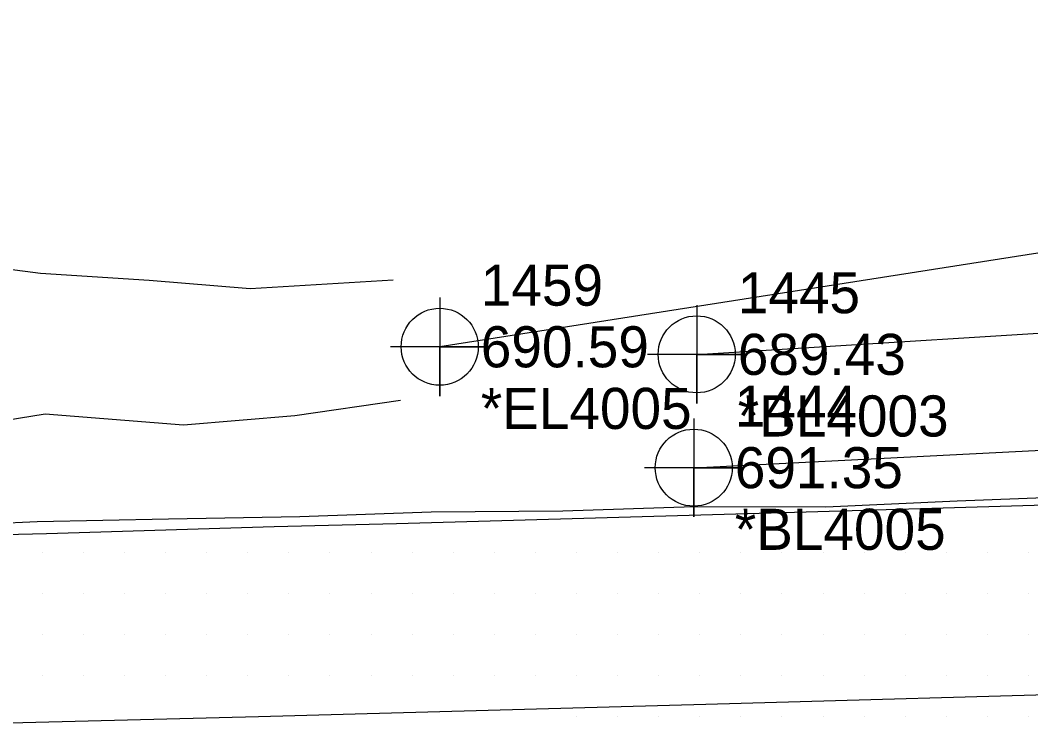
# Model space of a CAD drawing. Extents: x 1755643 to 1760494, y 736519 to 737621.
# Drawn here: x 1757879.9 to 1757941.4, y 736988 to 737031.1 of the extents above; entities that cross this region are included whole.
import ezdxf

# ---------------------------------------------------------------- set-up
doc = ezdxf.new("R2010")
doc.units = 0
for name, color, linetype in [('Exist Horizontal Alignment Direction Label', 7, 'Continuous'), ('Exist Railroads Standard Gauge', 7, 'Continuous'), ('Old_Level_1', 7, 'Continuous'), ('Old_Level_10', 7, 'Continuous'), ('Old_Level_2', 7, 'Continuous'), ('Old_Level_3', 7, 'Continuous'), ('Prop Dimension', 7, 'Continuous'), ('Prop EOT Dash', 7, 'Continuous'), ('Prop Horizontal Alignment Direction Label', 7, 'Continuous'), ('Prop Lane Lines', 7, 'Continuous'), ('Scratch_Level_1', 7, 'Continuous'), ('Scratch_Level_2', 7, 'Continuous'), ('Scratch_Level_5', 7, 'Continuous'), ('Scratch_Level_9', 7, 'Continuous')]:
    doc.layers.add(name, color=color, linetype=linetype)

msp = doc.modelspace()

# ---------------------------------------------------------------- linework, layer by layer
at = {"layer": 'Exist Railroads Standard Gauge'}
for points in [[(1757872.85, 737016.817), (1757881.144, 737015.738), (1757887.747, 737015.311), (1757893.894, 737014.806), (1757902.587, 737015.337)], [(1757871.29, 737005.551), (1757881.423, 737007.182), (1757889.839, 737006.52), (1757896.606, 737007.081), (1757903.049, 737008.017)]]:
    msp.add_lwpolyline(points, dxfattribs=at)
at = {"layer": 'Old_Level_10'}
msp.add_lwpolyline([(1757921.064, 737013.807), (1757921.064, 737007.807), (1757921.064, 737010.807), (1757924.064, 737010.807), (1757918.064, 737010.807)], dxfattribs=at)
msp.add_circle((1757921.064, 737010.807), 2.344, dxfattribs=at)
at = {"layer": 'Prop Dimension'}
msp.add_lwpolyline([(1757921.064, 737010.807), (1757950.306, 737012.625), (1757968.716, 737016.095), (1757981.467, 737016.866)], dxfattribs=at)
at = {"layer": 'Prop Lane Lines'}
for points in [[(1757905.428, 737014.267), (1757905.428, 737008.267), (1757905.428, 737011.267), (1757908.428, 737011.267), (1757902.428, 737011.267)], [(1757920.884, 737006.91), (1757920.884, 737000.91), (1757920.884, 737003.91), (1757923.884, 737003.91), (1757917.884, 737003.91)]]:
    msp.add_lwpolyline(points, dxfattribs=at)
for centre in [(1757905.428, 737011.267), (1757920.884, 737003.91)]:
    msp.add_circle(centre, 2.344, dxfattribs=at)
at = {"layer": 'Scratch_Level_1'}
msp.add_lwpolyline([(1757864.939, 737000.079), (1757872.936, 737000.271), (1757880.928, 737000.627), (1757888.921, 737000.805), (1757896.919, 737000.945), (1757904.914, 737001.227), (1757912.914, 737001.293), (1757920.91, 737001.55), (1757928.913, 737001.535), (1757936.905, 737001.889), (1757944.899, 737002.192), (1757952.901, 737002.259), (1757960.901, 737002.367), (1757968.898, 737002.553), (1757976.895, 737002.778), (1757984.893, 737002.981), (1757992.889, 737003.22), (1758000.882, 737003.602)], dxfattribs=at)
at = {"layer": 'Scratch_Level_2'}
for p, q in [((1757881.25, 736998.75), (1757881.25, 736998.75)), ((1757883.75, 736998.75), (1757883.75, 736998.75)), ((1757886.25, 736998.75), (1757886.25, 736998.75)), ((1757888.75, 736998.75), (1757888.75, 736998.75)), ((1757891.25, 736998.75), (1757891.25, 736998.75)), ((1757893.75, 736998.75), (1757893.75, 736998.75)), ((1757896.25, 736998.75), (1757896.25, 736998.75)), ((1757898.75, 736998.75), (1757898.75, 736998.75)), ((1757901.25, 736998.75), (1757901.25, 736998.75)), ((1757903.75, 736998.75), (1757903.75, 736998.75)), ((1757906.25, 736998.75), (1757906.25, 736998.75)), ((1757908.75, 736998.75), (1757908.75, 736998.75)), ((1757911.25, 736998.75), (1757911.25, 736998.75)), ((1757913.75, 736998.75), (1757913.75, 736998.75)), ((1757916.25, 736998.75), (1757916.25, 736998.75)), ((1757918.75, 736998.75), (1757918.75, 736998.75)), ((1757921.25, 736998.75), (1757921.25, 736998.75)), ((1757923.75, 736998.75), (1757923.75, 736998.75)), ((1757926.25, 736998.75), (1757926.25, 736998.75)), ((1757928.75, 736998.75), (1757928.75, 736998.75)), ((1757931.25, 736998.75), (1757931.25, 736998.75)), ((1757933.75, 736998.75), (1757933.75, 736998.75)), ((1757936.25, 736998.75), (1757936.25, 736998.75)), ((1757938.75, 736998.75), (1757938.75, 736998.75)), ((1757941.25, 736998.75), (1757941.25, 736998.75)), ((1757881.25, 736996.25), (1757881.25, 736996.25)), ((1757883.75, 736996.25), (1757883.75, 736996.25)), ((1757886.25, 736996.25), (1757886.25, 736996.25)), ((1757888.75, 736996.25), (1757888.75, 736996.25)), ((1757891.25, 736996.25), (1757891.25, 736996.25)), ((1757893.75, 736996.25), (1757893.75, 736996.25)), ((1757896.25, 736996.25), (1757896.25, 736996.25)), ((1757898.75, 736996.25), (1757898.75, 736996.25)), ((1757901.25, 736996.25), (1757901.25, 736996.25)), ((1757903.75, 736996.25), (1757903.75, 736996.25)), ((1757906.25, 736996.25), (1757906.25, 736996.25)), ((1757908.75, 736996.25), (1757908.75, 736996.25)), ((1757911.25, 736996.25), (1757911.25, 736996.25)), ((1757913.75, 736996.25), (1757913.75, 736996.25)), ((1757916.25, 736996.25), (1757916.25, 736996.25)), ((1757918.75, 736996.25), (1757918.75, 736996.25)), ((1757921.25, 736996.25), (1757921.25, 736996.25)), ((1757923.75, 736996.25), (1757923.75, 736996.25)), ((1757926.25, 736996.25), (1757926.25, 736996.25)), ((1757928.75, 736996.25), (1757928.75, 736996.25)), ((1757931.25, 736996.25), (1757931.25, 736996.25)), ((1757933.75, 736996.25), (1757933.75, 736996.25)), ((1757936.25, 736996.25), (1757936.25, 736996.25)), ((1757938.75, 736996.25), (1757938.75, 736996.25)), ((1757941.25, 736996.25), (1757941.25, 736996.25)), ((1757881.25, 736993.75), (1757881.25, 736993.75)), ((1757883.75, 736993.75), (1757883.75, 736993.75)), ((1757886.25, 736993.75), (1757886.25, 736993.75)), ((1757888.75, 736993.75), (1757888.75, 736993.75)), ((1757891.25, 736993.75), (1757891.25, 736993.75)), ((1757893.75, 736993.75), (1757893.75, 736993.75)), ((1757896.25, 736993.75), (1757896.25, 736993.75)), ((1757898.75, 736993.75), (1757898.75, 736993.75)), ((1757901.25, 736993.75), (1757901.25, 736993.75)), ((1757903.75, 736993.75), (1757903.75, 736993.75)), ((1757906.25, 736993.75), (1757906.25, 736993.75)), ((1757908.75, 736993.75), (1757908.75, 736993.75)), ((1757911.25, 736993.75), (1757911.25, 736993.75)), ((1757913.75, 736993.75), (1757913.75, 736993.75)), ((1757916.25, 736993.75), (1757916.25, 736993.75)), ((1757918.75, 736993.75), (1757918.75, 736993.75)), ((1757921.25, 736993.75), (1757921.25, 736993.75)), ((1757923.75, 736993.75), (1757923.75, 736993.75)), ((1757926.25, 736993.75), (1757926.25, 736993.75)), ((1757928.75, 736993.75), (1757928.75, 736993.75)), ((1757931.25, 736993.75), (1757931.25, 736993.75)), ((1757933.75, 736993.75), (1757933.75, 736993.75)), ((1757936.25, 736993.75), (1757936.25, 736993.75)), ((1757938.75, 736993.75), (1757938.75, 736993.75)), ((1757941.25, 736993.75), (1757941.25, 736993.75)), ((1757881.25, 736991.25), (1757881.25, 736991.25)), ((1757883.75, 736991.25), (1757883.75, 736991.25)), ((1757886.25, 736991.25), (1757886.25, 736991.25)), ((1757888.75, 736991.25), (1757888.75, 736991.25)), ((1757891.25, 736991.25), (1757891.25, 736991.25)), ((1757893.75, 736991.25), (1757893.75, 736991.25)), ((1757896.25, 736991.25), (1757896.25, 736991.25)), ((1757898.75, 736991.25), (1757898.75, 736991.25)), ((1757901.25, 736991.25), (1757901.25, 736991.25)), ((1757903.75, 736991.25), (1757903.75, 736991.25)), ((1757906.25, 736991.25), (1757906.25, 736991.25)), ((1757908.75, 736991.25), (1757908.75, 736991.25)), ((1757911.25, 736991.25), (1757911.25, 736991.25)), ((1757913.75, 736991.25), (1757913.75, 736991.25)), ((1757916.25, 736991.25), (1757916.25, 736991.25)), ((1757918.75, 736991.25), (1757918.75, 736991.25)), ((1757921.25, 736991.25), (1757921.25, 736991.25)), ((1757923.75, 736991.25), (1757923.75, 736991.25)), ((1757926.25, 736991.25), (1757926.25, 736991.25)), ((1757928.75, 736991.25), (1757928.75, 736991.25)), ((1757931.25, 736991.25), (1757931.25, 736991.25)), ((1757933.75, 736991.25), (1757933.75, 736991.25)), ((1757936.25, 736991.25), (1757936.25, 736991.25)), ((1757938.75, 736991.25), (1757938.75, 736991.25)), ((1757941.25, 736991.25), (1757941.25, 736991.25)), ((1757913.75, 736988.75), (1757913.75, 736988.75)), ((1757916.25, 736988.75), (1757916.25, 736988.75)), ((1757918.75, 736988.75), (1757918.75, 736988.75)), ((1757921.25, 736988.75), (1757921.25, 736988.75)), ((1757923.75, 736988.75), (1757923.75, 736988.75)), ((1757926.25, 736988.75), (1757926.25, 736988.75)), ((1757928.75, 736988.75), (1757928.75, 736988.75)), ((1757931.25, 736988.75), (1757931.25, 736988.75)), ((1757933.75, 736988.75), (1757933.75, 736988.75)), ((1757936.25, 736988.75), (1757936.25, 736988.75)), ((1757938.75, 736988.75), (1757938.75, 736988.75)), ((1757941.25, 736988.75), (1757941.25, 736988.75))]:
    msp.add_line(p, q, dxfattribs=at)
at = {"layer": 'Scratch_Level_5'}
for points in [[(1757864.463, 736999.502), (1757881.496, 736999.898), (1757895.349, 737000.323), (1757902.806, 737000.519), (1757928.432, 737001.252), (1757948.524, 737001.834), (1757969.145, 737002.413), (1757999.376, 737003.236), (1758030.724, 737004.002), (1758039.045, 737004.185), (1758058.137, 737004.631), (1758064.691, 737004.753)], [(1757864.901, 736988.021), (1757894.4, 736988.775), (1757921.615, 736989.52), (1757947.433, 736990.242), (1757966.325, 736990.768), (1757986.395, 736991.257), (1757996.913, 736991.496), (1758005.687, 736991.753), (1758027.312, 736992.264), (1758052.981, 736992.866), (1758064.805, 736993.189)]]:
    msp.add_lwpolyline(points, dxfattribs=at)
at = {"layer": 'Scratch_Level_9'}
msp.add_lwpolyline([(1757920.884, 737003.91), (1757950.843, 737005.426), (1757979.995, 737009.419), (1757991.841, 737005.818), (1758004.867, 737007.71), (1758008.37, 737016.744), (1758001.065, 737025.127), (1757988.037, 737031.139), (1757974.018, 737023.93), (1757974.149, 737017.615), (1757944.532, 737017.395), (1757905.428, 737011.267)], dxfattribs=at)

# ---------------------------------------------------------------- texts
at = {"layer": 'Exist Horizontal Alignment Direction Label'}
for s, p in [('*EL4005', (1757907.928, 737006.267)), ('*BL4005', (1757923.384, 736998.91))]:
    msp.add_text(s, height=2.5, dxfattribs=at).set_placement(p)
at = {"layer": 'Old_Level_1'}
msp.add_text('1445', height=2.5, dxfattribs=at).set_placement((1757923.564, 737013.307))
at = {"layer": 'Old_Level_2'}
msp.add_text('689.43', height=2.5, dxfattribs=at).set_placement((1757923.564, 737009.557))
at = {"layer": 'Old_Level_3'}
for s, p in [('690.59', (1757907.928, 737010.017)), ('691.35', (1757923.384, 737002.66))]:
    msp.add_text(s, height=2.5, dxfattribs=at).set_placement(p)
at = {"layer": 'Prop EOT Dash'}
for s, p in [('1459', (1757907.928, 737013.767)), ('1444', (1757923.384, 737006.41))]:
    msp.add_text(s, height=2.5, dxfattribs=at).set_placement(p)
at = {"layer": 'Prop Horizontal Alignment Direction Label'}
msp.add_text('*BL4003', height=2.5, dxfattribs=at).set_placement((1757923.564, 737005.807))

doc.saveas('drawing.dxf')
